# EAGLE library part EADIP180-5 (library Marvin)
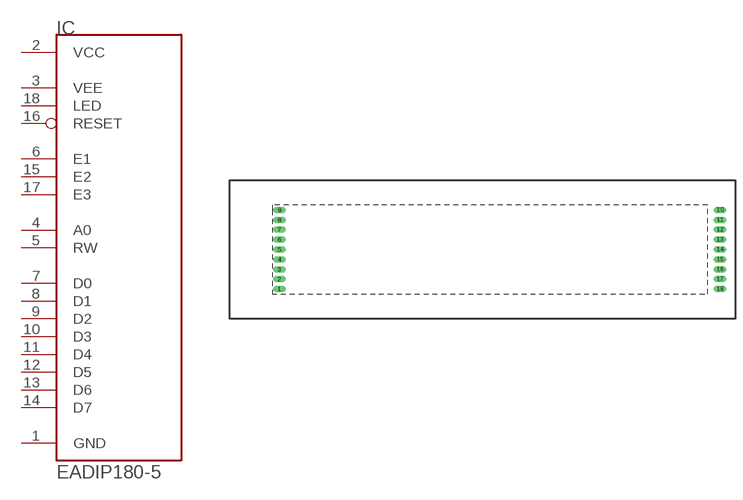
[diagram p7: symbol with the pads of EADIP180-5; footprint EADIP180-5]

Designator prefix IC

## EADIP180-5  [EADIP180-5]
1  GND
2  VCC
3  VEE
4  A0
5  RW
6  E1
7  D0
8  D1
9  D2
10  D3
11  D4
12  D5
13  D6
14  D7
15  E2
16  RESET
17  E3
18  LED

## Footprint EADIP180-5 (pad centres in mm)
drill 0.8 long: 1 -44.5,-8; 2 -44.5,-6; 3 -44.5,-4; 4 -44.5,-2; 5 -44.5,0; 6 -44.5,2; 7 -44.5,4; 8 -44.5,6; 9 -44.5,8; 10 44.5,8; 11 44.5,6; 12 44.5,4; 13 44.5,2; 14 44.5,0; 15 44.5,-2; 16 44.5,-4; 17 44.5,-6; 18 44.5,-8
